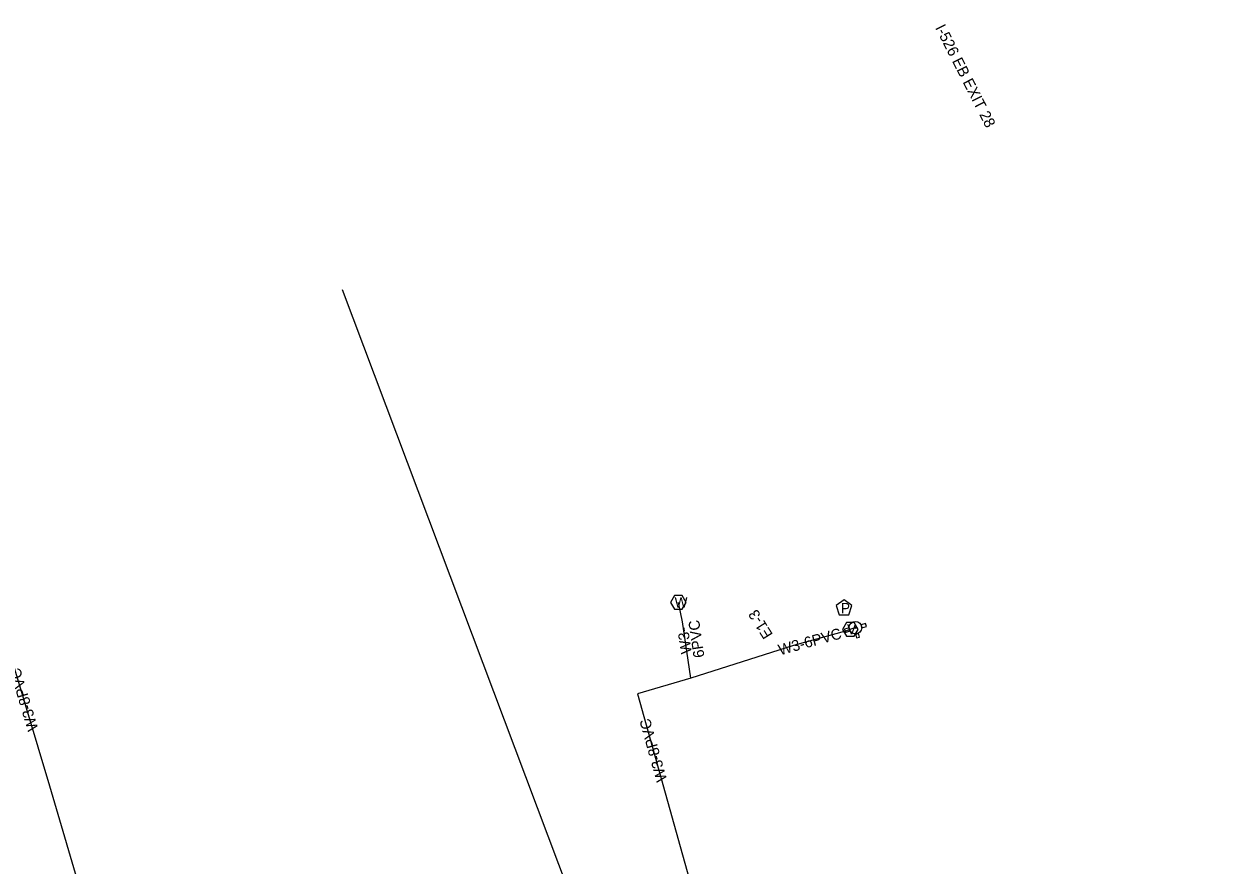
# Model space of a CAD drawing. Extents: x 2336688 to 2352634, y 362473 to 369571.
# Drawn here: x 2348250.9 to 2348691.6, y 367821.8 to 368130.8 of the extents above; entities that cross this region are included whole.
import ezdxf

# ---------------------------------------------------------------- set-up
doc = ezdxf.new("R2010")
doc.units = 0
for name, color, linetype in [('Default', 7, 'Continuous'), ('RD_EX_DV_Prop', 7, 'Continuous'), ('RD_PD_CstnLmt', 7, 'Continuous'), ('RD_Sketch2', 7, 'Continuous'), ('RD_TX_Misc1', 7, 'Continuous')]:
    doc.layers.add(name, color=color, linetype=linetype)

msp = doc.modelspace()

# ---------------------------------------------------------------- linework, layer by layer
at = {"layer": 'Default'}
msp.add_line((2348691.59, 367174.54), (2348367.83, 368033.25), dxfattribs=at)
msp.add_line((2348691.59, 367174.54), (2348367.83, 368033.25), dxfattribs=at)
msp.add_line((2348691.59, 367174.54), (2348367.83, 368033.25), dxfattribs=at)
at = {"layer": 'RD_Sketch2'}
for p, q in [((2348553.93, 367909.14), (2348552.18, 367908.66)), ((2348559.98, 367910.81), (2348558.29, 367910.34)), ((2348558.55, 367909.21), (2348560.28, 367909.69)), ((2348560.28, 367909.69), (2348559.98, 367910.81)), ((2348552.18, 367908.66), (2348552.49, 367907.54)), ((2348552.49, 367907.54), (2348554.28, 367908.04)), ((2348556.23, 367906.96), (2348556.62, 367905.51)), ((2348556.62, 367905.51), (2348557.74, 367905.82)), ((2348557.74, 367905.82), (2348557.35, 367907.24))]:
    msp.add_line(p, q, dxfattribs=at)
for points in [[(2348556.24, 367909.26), (2348552.57, 367908), (2348533.51, 367902.75), (2348495.8, 367890.75), (2348476.22, 367884.91), (2348498.22, 367806.14), (2348509.39, 367769.77), (2348452.39, 367753.96), (2348412.83, 367742.03), (2348383.64, 367733), (2348325.81, 367717.84), (2348294.09, 367735.62), (2348285.99, 367763.92), (2348272.89, 367808.65), (2348260.35, 367851.09), (2348247.19, 367895.19), (2348233.68, 367941.56), (2348220.7, 367989.93), (2348226.95, 367991.6), (2348244.37, 367996.56), (2348246.31, 367997.03), (2348247.28, 367997.26)], [(2348495.8, 367890.75), (2348492.74, 367911.45), (2348491.21, 367918.51)]]:
    msp.add_lwpolyline(points, dxfattribs=at)
for points in [[(2348494.09, 367918.51), (2348492.65, 367921.01), (2348489.76, 367921.01), (2348488.32, 367918.51), (2348489.76, 367916.01), (2348492.65, 367916.01)], [(2348552.04, 367919.49), (2348549.14, 367917.39), (2348550.24, 367913.98), (2348553.83, 367913.98), (2348554.94, 367917.39)], [(2348557.24, 367908.63), (2348555.79, 367911.13), (2348552.91, 367911.13), (2348551.46, 367908.63), (2348552.91, 367906.13), (2348555.79, 367906.13)]]:
    msp.add_lwpolyline(points, close=True, dxfattribs=at)
for radius in [2.31, 0.289]:
    msp.add_circle((2348556.24, 367909.26), radius, dxfattribs=at)
for start, end in [(183.0845, 212.0608), (358.7382, 27.7145), (269.645, 298.6123)]:
    msp.add_arc((2348556.24, 367909.26), 2.31, start, end, dxfattribs=at)

# ---------------------------------------------------------------- texts
at = {"layer": 'RD_EX_DV_Prop'}
msp.add_text('E1-3', height=4, rotation=122.1893, dxfattribs=at).set_placement((2348526.05, 367906.74))
at = {"layer": 'RD_PD_CstnLmt'}
for s, rotation, p in [('W3-', 98.3973, (2348496.16, 367899.96)), ('6PVC', 98.3973, (2348500.83, 367898.5)), ('W3-6PVC', 15.3995, (2348528.55, 367899.07)), ('W3-8PVC', 106.611, (2348256.19, 367872.02)), ('W3-8PVC', 105.6059, (2348487.12, 367853.33))]:
    msp.add_text(s, height=4, rotation=rotation, dxfattribs=at).set_placement(p)
at = {"layer": 'RD_Sketch2'}
for s, p in [('W', (2348489.82, 367916.63)), ('V', (2348553.14, 367906.75))]:
    msp.add_text(s, height=3.75, dxfattribs=at).set_placement(p)
msp.add_text('P', height=3.75, rotation=360, dxfattribs=at).set_placement((2348550.89, 367914.57))
at = {"layer": 'RD_TX_Misc1'}
msp.add_text('I-526 EB EXIT 28', height=4, rotation=296.9827, dxfattribs=at).set_placement((2348585.42, 368129.47))

doc.saveas('drawing.dxf')
